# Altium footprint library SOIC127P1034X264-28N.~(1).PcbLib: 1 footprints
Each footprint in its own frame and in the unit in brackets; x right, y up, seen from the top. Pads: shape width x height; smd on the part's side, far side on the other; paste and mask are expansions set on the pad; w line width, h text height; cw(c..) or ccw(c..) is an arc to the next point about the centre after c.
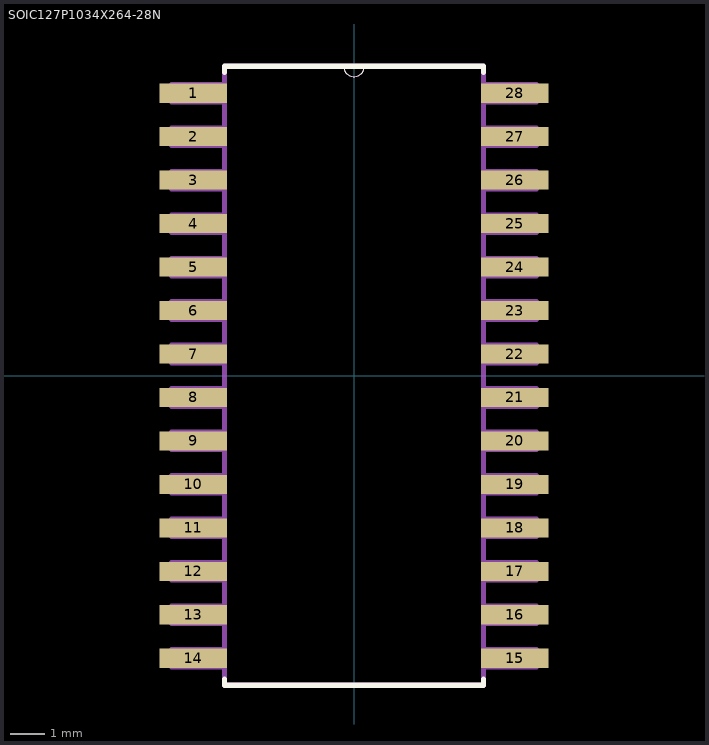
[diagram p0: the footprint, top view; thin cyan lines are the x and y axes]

## SOIC127P1034X264-28N [mil]
pads (28):
  rect 78x22 smd: 1(-185,325) 2(-185,275) 3(-185,225) 4(-185,175) 5(-185,125) 6(-185,75) 7(-185,25) 8(-185,-25) 9(-185,-75) 10(-185,-125) 11(-185,-175) 12(-185,-225) 13(-185,-275) 14(-185,-325) 15(185,-325) 16(185,-275) 17(185,-225) 18(185,-175) 19(185,-125) 20(185,-75) 21(185,-25) 22(185,25) 23(185,75) 24(185,125) 25(185,175) 26(185,225) 27(185,275) 28(185,325)
Top Overlay:
  lines w0: -12,356 ccw(c0,356) 12,356
  lines w6: -149,-349 -149,-356 149,-356 149,-349 ; -149,349 -149,356 -12,356 12,356 149,356 149,349
Assembly Top:
  lines w0: -12,356 ccw(c0,356) 12,356
  lines w6: -210,-335 -210,-315 -149,-315 -149,-335 -210,-335 ; -210,-285 -210,-265 -149,-265 -149,-285 -210,-285 ; -210,-235 -210,-215 -149,-215 -149,-235 -210,-235 ; -210,-185 -210,-165 -149,-165 -149,-185 -210,-185 ; -210,-135 -210,-115 -149,-115 -149,-135 -210,-135 ; -210,-85 -210,-65 -149,-65 -149,-85 -210,-85 ; -210,-35 -210,-15 -149,-15 -149,-35 -210,-35 ; -210,15 -210,35 -149,35 -149,15 -210,15 ; -210,65 -210,85 -149,85 -149,65 -210,65 ; -210,115 -210,135 -149,135 -149,115 -210,115 ; -210,165 -210,185 -149,185 -149,165 -210,165 ; -210,215 -210,235 -149,235 -149,215 -210,215 ; -210,265 -210,285 -149,285 -149,265 -210,265 ; -210,315 -210,335 -149,335 -149,315 -210,315 ; -149,-356 149,-356 149,356 12,356 -12,356 -149,356 -149,-356 ; 149,-335 149,-315 210,-315 210,-335 149,-335 ; 149,-285 149,-265 210,-265 210,-285 149,-285 ; 149,-235 149,-215 210,-215 210,-235 149,-235 ; 149,-185 149,-165 210,-165 210,-185 149,-185 ; 149,-135 149,-115 210,-115 210,-135 149,-135 ; 149,-85 149,-65 210,-65 210,-85 149,-85 ; 149,-35 149,-15 210,-15 210,-35 149,-35 ; 149,15 149,35 210,35 210,15 149,15 ; 149,65 149,85 210,85 210,65 149,65 ; 149,115 149,135 210,135 210,115 149,115 ; 149,165 149,185 210,185 210,165 149,165 ; 149,215 149,235 210,235 210,215 149,215 ; 149,265 149,285 210,285 210,265 149,265 ; 149,315 149,335 210,335 210,315 149,315
3D body "step_temp.STEP": height 104.33, standoff 0, extent -202.76,-352.36 202.76,352.36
